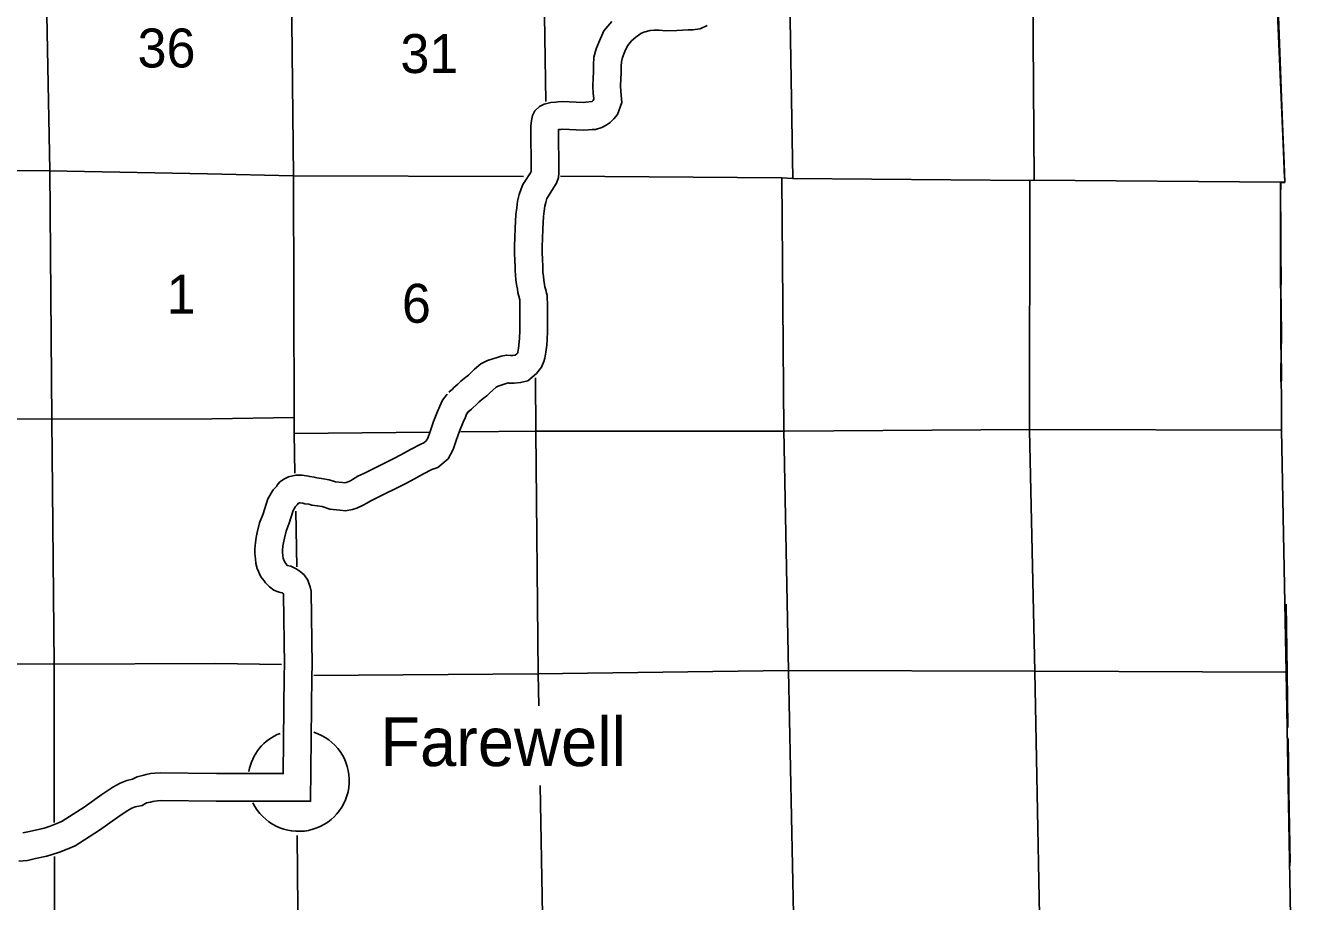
# Model space of a CAD drawing. Extents: x 77230 to 630905, y 790554 to 1662844.
# Drawn here: x 474126 to 501624, y 1600152 to 1619160 of the extents above; entities that cross this region are included whole.
import ezdxf

# ---------------------------------------------------------------- set-up
doc = ezdxf.new("R2010")
doc.units = 0
for name, color, linetype in [('Level 15', 7, 'Continuous'), ('Level 16', 7, 'Continuous'), ('Level 18', 7, 'Continuous'), ('Level 22', 7, 'Continuous'), ('Level 26', 7, 'Continuous'), ('Level 43', 7, 'Continuous')]:
    doc.layers.add(name, color=color, linetype=linetype)

msp = doc.modelspace()

# ---------------------------------------------------------------- linework, layer by layer
at = {"layer": 'Level 15'}
for points in [[(479717, 1636912), (479774, 1631910), (479834, 1626579), (479884, 1621257), (479943, 1615888), (479960, 1610654), (479956, 1610308), (479974, 1609444)], [(464632, 1616087), (469369, 1616046), (474647, 1616003), (478077, 1615938)], [(478077, 1615938), (479939, 1615894), (484938, 1615884)], [(485740, 1615890), (490537, 1615850), (490777, 1615840), (495918, 1615795), (496015, 1615798), (501358, 1615756)], [(479992, 1608622), (480018, 1607418)], [(480025, 1601590), (480035, 1600000), (480046, 1599824), (480090, 1596156)]]:
    msp.add_lwpolyline(points, dxfattribs=at)
at = {"layer": 'Level 16'}
for points in [[(474459, 1636579), (474453, 1631902), (474480, 1626616), (474553, 1621263), (474655, 1616017), (474702, 1610602), (474752, 1605292), (474754, 1601870)], [(485146, 1635809), (485219, 1631833), (485283, 1626572), (485361, 1621247), (485418, 1617511)], [(490692, 1621012), (490777, 1615840)], [(495988, 1619908), (496015, 1615798)], [(490537, 1615850), (490585, 1610380), (490684, 1605162), (490796, 1599882), (490880, 1596386)], [(495918, 1615795), (495916, 1610368), (496027, 1605143), (496129, 1599851), (496195, 1596422)], [(485198, 1611511), (485206, 1610350), (485251, 1605100), (485264, 1604399)], [(478175, 1610622), (474718, 1610618), (469378, 1610658), (466118, 1610615)], [(479960, 1610654), (478175, 1610622)], [(482911, 1610334), (479956, 1610308)], [(501382, 1610380), (495921, 1610392), (490603, 1610358), (485220, 1610355), (483573, 1610340)], [(478249, 1605315), (474744, 1605306), (469453, 1605337), (464146, 1605335), (461603, 1605328)], [(479681, 1605293), (478249, 1605315)], [(501484, 1605131), (496035, 1605152), (490680, 1605168), (485242, 1605090), (480383, 1605056)], [(485295, 1602672), (485345, 1599863), (485400, 1596307)], [(474755, 1601128), (474756, 1599966), (474801, 1596072)]]:
    msp.add_lwpolyline(points, dxfattribs=at)
at = {"layer": 'Level 18'}
msp.add_lwpolyline([(501006, 1635374), (501100, 1631624), (501214, 1626409), (501225, 1621103), (501451, 1615759), (501358, 1615756), (501382, 1610380), (501484, 1605131), (501575, 1599831), (501624, 1596559)], dxfattribs=at)
msp.add_lwpolyline([(501006, 1635374), (501100, 1631624), (501214, 1626409), (501225, 1621103), (501451, 1615759), (501358, 1615756), (501382, 1610380), (501484, 1605131), (501575, 1599831), (501624, 1596559)], dxfattribs=at)
at = {"layer": 'Level 22'}
for points in [[(486850, 1619244), (486677, 1619038), (486582, 1618822), (486513, 1618649), (486463, 1618467), (486452, 1618294), (486452, 1618142), (486445, 1618019), (486442, 1617832), (486450, 1617686), (486458, 1617569), (486445, 1617533), (486425, 1617511), (486424, 1617510), (486286, 1617490), (486227, 1617487), (485771, 1617507), (485684, 1617500), (485633, 1617494), (485525, 1617488), (485384, 1617449), (485283, 1617401), (485180, 1617303), (485133, 1617206), (485105, 1617096), (485091, 1616971), (485099, 1615986), (485084, 1615959), (485046, 1615897), (485005, 1615835), (484922, 1615711), (484882, 1615612), (484840, 1615489), (484804, 1615343), (484787, 1615205), (484769, 1615060), (484757, 1614763), (484749, 1614558), (484743, 1614380), (484737, 1614226), (484748, 1614051), (484753, 1613932), (484751, 1613845), (484760, 1613744), (484771, 1613642), (484783, 1613541), (484802, 1613437), (484814, 1613367), (484834, 1613285), (484852, 1613203), (484852, 1613201), (484852, 1613201), (484857, 1613117), (484856, 1612953), (484856, 1612769), (484855, 1612533), (484851, 1612375), (484843, 1612294), (484823, 1612156), (484811, 1612069), (484809, 1612062), (484804, 1612049), (484792, 1612034), (484754, 1612003), (484707, 1611998), (484652, 1611999), (484564, 1612007), (484447, 1611987), (484362, 1611955), (484272, 1611927), (484155, 1611890), (484012, 1611815), (483869, 1611701), (483775, 1611609), (483740, 1611574), (483683, 1611530), (483576, 1611439), (483512, 1611379), (483425, 1611303), (483391, 1611269), (483315, 1611200)], [(486850, 1619244), (486677, 1619038), (486582, 1618822), (486513, 1618649), (486463, 1618467), (486452, 1618294), (486452, 1618142), (486445, 1618019), (486442, 1617832), (486450, 1617686), (486458, 1617569), (486445, 1617533), (486425, 1617511), (486424, 1617510), (486286, 1617490), (486227, 1617487), (485771, 1617507), (485684, 1617500), (485633, 1617494), (485525, 1617488), (485384, 1617449), (485283, 1617401), (485180, 1617303), (485133, 1617206), (485105, 1617096), (485091, 1616971), (485099, 1615986), (485084, 1615959), (485046, 1615897), (485005, 1615835), (484922, 1615711), (484882, 1615612), (484840, 1615489), (484804, 1615343), (484787, 1615205), (484769, 1615060), (484757, 1614763), (484749, 1614558), (484743, 1614380), (484737, 1614226), (484748, 1614051), (484753, 1613932), (484751, 1613845), (484760, 1613744), (484771, 1613642), (484783, 1613541), (484802, 1613437), (484814, 1613367), (484834, 1613285), (484852, 1613203), (484852, 1613201), (484852, 1613201), (484857, 1613117), (484856, 1612953), (484856, 1612769), (484855, 1612533), (484851, 1612375), (484843, 1612294), (484823, 1612156), (484811, 1612069), (484809, 1612062), (484804, 1612049), (484792, 1612034), (484754, 1612003), (484707, 1611998), (484652, 1611999), (484564, 1612007), (484447, 1611987), (484362, 1611955), (484272, 1611927), (484155, 1611890), (484012, 1611815), (483869, 1611701), (483775, 1611609), (483740, 1611574), (483683, 1611530), (483576, 1611439), (483512, 1611379), (483425, 1611303), (483391, 1611269), (483315, 1611200)], [(488923, 1619153), (488765, 1619083), (488608, 1619066), (488506, 1619060), (488264, 1619050), (488022, 1619043), (487880, 1619052), (487771, 1619055), (487680, 1619046), (487549, 1619011), (487481, 1618982), (487373, 1618905), (487281, 1618824), (487192, 1618718), (487135, 1618589), (487083, 1618459), (487058, 1618369), (487052, 1618273), (487052, 1618124), (487045, 1617999), (487043, 1617845), (487049, 1617722), (487065, 1617487), (486973, 1617223), (486893, 1617132), (486815, 1617050), (486726, 1616991), (486636, 1616945), (486498, 1616901), (486422, 1616904), (486346, 1616892), (486230, 1616886), (485780, 1616906), (485743, 1616903), (485692, 1616897), (485699, 1615989), (485699, 1615953), (485691, 1615856), (485648, 1615738), (485602, 1615656), (485553, 1615576), (485506, 1615505), (485455, 1615428), (485444, 1615402), (485416, 1615320), (485395, 1615234), (485382, 1615131), (485367, 1615011), (485356, 1614739), (485348, 1614535), (485342, 1614360), (485338, 1614234), (485347, 1614080), (485353, 1613939), (485352, 1613865), (485357, 1613803), (485367, 1613712), (485377, 1613629), (485392, 1613541), (485401, 1613491), (485419, 1613421), (485434, 1613348), (485447, 1613305), (485451, 1613237), (485457, 1613132), (485456, 1612952), (485456, 1612767), (485455, 1612523), (485450, 1612340), (485439, 1612224), (485418, 1612073), (485400, 1611944), (485378, 1611870), (485329, 1611743), (485219, 1611608), (485030, 1611452), (484870, 1611411), (484729, 1611398), (484620, 1611400), (484595, 1611402), (484558, 1611388), (484453, 1611355), (484386, 1611334), (484341, 1611310), (484266, 1611250), (484198, 1611184), (484141, 1611126), (484063, 1611065), (483975, 1610990), (483913, 1610932), (483837, 1610866), (483807, 1610835), (483716, 1610754)], [(488923, 1619153), (488765, 1619083), (488608, 1619066), (488506, 1619060), (488264, 1619050), (488022, 1619043), (487880, 1619052), (487771, 1619055), (487680, 1619046), (487549, 1619011), (487481, 1618982), (487373, 1618905), (487281, 1618824), (487192, 1618718), (487135, 1618589), (487083, 1618459), (487058, 1618369), (487052, 1618273), (487052, 1618124), (487045, 1617999), (487043, 1617845), (487049, 1617722), (487065, 1617487), (486973, 1617223), (486893, 1617132), (486815, 1617050), (486726, 1616991), (486636, 1616945), (486498, 1616901), (486422, 1616904), (486346, 1616892), (486230, 1616886), (485780, 1616906), (485743, 1616903), (485692, 1616897), (485699, 1615989), (485699, 1615953), (485691, 1615856), (485648, 1615738), (485602, 1615656), (485553, 1615576), (485506, 1615505), (485455, 1615428), (485444, 1615402), (485416, 1615320), (485395, 1615234), (485382, 1615131), (485367, 1615011), (485356, 1614739), (485348, 1614535), (485342, 1614360), (485338, 1614234), (485347, 1614080), (485353, 1613939), (485352, 1613865), (485357, 1613803), (485367, 1613712), (485377, 1613629), (485392, 1613541), (485401, 1613491), (485419, 1613421), (485434, 1613348), (485447, 1613305), (485451, 1613237), (485457, 1613132), (485456, 1612952), (485456, 1612767), (485455, 1612523), (485450, 1612340), (485439, 1612224), (485418, 1612073), (485400, 1611944), (485378, 1611870), (485329, 1611743), (485219, 1611608), (485030, 1611452), (484870, 1611411), (484729, 1611398), (484620, 1611400), (484595, 1611402), (484558, 1611388), (484453, 1611355), (484386, 1611334), (484341, 1611310), (484266, 1611250), (484198, 1611184), (484141, 1611126), (484063, 1611065), (483975, 1610990), (483913, 1610932), (483837, 1610866), (483807, 1610835), (483716, 1610754)], [(483277, 1611159), (483178, 1611030), (483122, 1610901), (483072, 1610785), (482985, 1610568), (482911, 1610350), (482859, 1610207), (482826, 1610146), (482775, 1610103), (482704, 1610078), (482480, 1609958), (482288, 1609853), (482110, 1609759), (481471, 1609439), (481337, 1609380), (481226, 1609309), (481180, 1609283), (481108, 1609249), (481089, 1609244), (481051, 1609237), (481011, 1609242), (480858, 1609255), (480717, 1609303), (480549, 1609334), (480449, 1609345), (480393, 1609360), (480299, 1609374), (480271, 1609380), (480132, 1609406), (479998, 1609401), (479835, 1609363), (479746, 1609325), (479645, 1609256), (479591, 1609183), (479573, 1609159), (479561, 1609143), (479505, 1609081), (479389, 1608890), (479285, 1608564), (479208, 1608369), (479159, 1608160), (479137, 1608050), (479117, 1607940), (479105, 1607801), (479106, 1607705), (479119, 1607588), (479128, 1607489), (479159, 1607377), (479238, 1607195), (479308, 1607112), (479336, 1607065), (479377, 1607025), (479420, 1606980), (479518, 1606909), (479589, 1606882), (479655, 1606860), (479696, 1606851), (479706, 1606847), (479720, 1606838), (479725, 1606822), (479726, 1606817), (479747, 1605283), (479739, 1605064), (479721, 1602931), (478270, 1602932)], [(483277, 1611159), (483178, 1611030), (483122, 1610901), (483072, 1610785), (482985, 1610568), (482911, 1610350), (482859, 1610207), (482826, 1610146), (482775, 1610103), (482704, 1610078), (482480, 1609958), (482288, 1609853), (482110, 1609759), (481471, 1609439), (481337, 1609380), (481226, 1609309), (481180, 1609283), (481108, 1609249), (481089, 1609244), (481051, 1609237), (481011, 1609242), (480858, 1609255), (480717, 1609303), (480549, 1609334), (480449, 1609345), (480393, 1609360), (480299, 1609374), (480271, 1609380), (480132, 1609406), (479998, 1609401), (479835, 1609363), (479746, 1609325), (479645, 1609256), (479591, 1609183), (479573, 1609159), (479561, 1609143), (479505, 1609081), (479389, 1608890), (479285, 1608564), (479208, 1608369), (479159, 1608160), (479137, 1608050), (479117, 1607940), (479105, 1607801), (479106, 1607705), (479119, 1607588), (479128, 1607489), (479159, 1607377), (479238, 1607195), (479308, 1607112), (479336, 1607065), (479377, 1607025), (479420, 1606980), (479518, 1606909), (479589, 1606882), (479655, 1606860), (479696, 1606851), (479706, 1606847), (479720, 1606838), (479725, 1606822), (479726, 1606817), (479747, 1605283), (479739, 1605064), (479721, 1602931), (478270, 1602932)], [(483754, 1610795), (483699, 1610723), (483673, 1610662), (483625, 1610554), (483548, 1610360), (483477, 1610152), (483408, 1609961), (483300, 1609760), (483077, 1609572), (482945, 1609527), (482766, 1609431), (482572, 1609324), (482383, 1609225), (481727, 1608896), (481621, 1608849), (481534, 1608794), (481456, 1608750), (481321, 1608686), (481224, 1608658), (481070, 1608631), (480950, 1608645), (480734, 1608664), (480566, 1608721), (480460, 1608740), (480339, 1608754), (480275, 1608771), (480189, 1608783), (480149, 1608792), (480087, 1608804), (480077, 1608804), (480052, 1608798), (480052, 1608798), (480024, 1608761), (479989, 1608722), (479939, 1608639), (479850, 1608362), (479782, 1608190), (479746, 1608034), (479726, 1607936), (479712, 1607861), (479706, 1607779), (479706, 1607739), (479716, 1607647), (479720, 1607599), (479726, 1607579), (479754, 1607513), (479798, 1607461), (479810, 1607440), (479885, 1607426), (480000, 1607372), (480086, 1607315), (480174, 1607241), (480256, 1607122), (480284, 1607042), (480305, 1606978), (480325, 1606884), (480347, 1605277), (480339, 1605051), (480316, 1602331), (478270, 1602332)], [(483754, 1610795), (483699, 1610723), (483673, 1610662), (483625, 1610554), (483548, 1610360), (483477, 1610152), (483408, 1609961), (483300, 1609760), (483077, 1609572), (482945, 1609527), (482766, 1609431), (482572, 1609324), (482383, 1609225), (481727, 1608896), (481621, 1608849), (481534, 1608794), (481456, 1608750), (481321, 1608686), (481224, 1608658), (481070, 1608631), (480950, 1608645), (480734, 1608664), (480566, 1608721), (480460, 1608740), (480339, 1608754), (480275, 1608771), (480189, 1608783), (480149, 1608792), (480087, 1608804), (480077, 1608804), (480052, 1608798), (480052, 1608798), (480024, 1608761), (479989, 1608722), (479939, 1608639), (479850, 1608362), (479782, 1608190), (479746, 1608034), (479726, 1607936), (479712, 1607861), (479706, 1607779), (479706, 1607739), (479716, 1607647), (479720, 1607599), (479726, 1607579), (479754, 1607513), (479798, 1607461), (479810, 1607440), (479885, 1607426), (480000, 1607372), (480086, 1607315), (480174, 1607241), (480256, 1607122), (480284, 1607042), (480305, 1606978), (480325, 1606884), (480347, 1605277), (480339, 1605051), (480316, 1602331), (478270, 1602332)], [(478273, 1602932), (477051, 1602947), (476939, 1602938), (476844, 1602929), (476748, 1602908), (476695, 1602893), (476551, 1602860), (476448, 1602807), (476330, 1602779), (476183, 1602722), (476023, 1602634), (475789, 1602479), (475399, 1602199), (475082, 1601999), (474926, 1601897), (474844, 1601863), (474666, 1601791), (474531, 1601749), (474442, 1601722), (474215, 1601672), (474075, 1601641)], [(478266, 1602332), (477071, 1602347), (476992, 1602341), (476938, 1602335), (476895, 1602326), (476844, 1602311), (476757, 1602292), (476658, 1602241), (476509, 1602205), (476437, 1602177), (476335, 1602121), (476130, 1601985), (475734, 1601701), (475406, 1601494), (475209, 1601365), (475073, 1601308), (474869, 1601225), (474705, 1601174), (474591, 1601141), (474345, 1601087), (474173, 1601048), (473988, 1601028)]]:
    msp.add_lwpolyline(points, dxfattribs=at)
at = {"layer": 'Level 26'}
for start, end in [(111.2653, 169.5598), (205.761, 72.678)]:
    msp.add_arc((480055, 1602777), 1100, start, end, dxfattribs=at)
at = {"layer": 'Level 43'}
msp.add_line((501367, 1615751), (501452, 1615752), dxfattribs=at)
for points in [[(501245, 1623346), (501248, 1622638), (501247, 1621106), (501256, 1620797), (501330, 1618968), (501327, 1618811), (501360, 1618045), (501440, 1616160), (501452, 1615752)], [(501252, 1621110), (501444, 1615844)], [(501367, 1615751), (501360, 1615420), (501363, 1613673), (501370, 1613235), (501368, 1612128)], [(501361, 1615672), (501367, 1614565)], [(501369, 1614314), (501373, 1613535)], [(501375, 1613222), (501380, 1612257)], [(501367, 1611834), (501366, 1611427)], [(501383, 1611817), (501385, 1611448)], [(501475, 1606545), (501505, 1605136), (501521, 1603953)], [(501482, 1606603), (501506, 1605120), (501518, 1603929)], [(501521, 1603706), (501569, 1601003)], [(501525, 1603679), (501563, 1600927)]]:
    msp.add_lwpolyline(points, dxfattribs=at)

# ---------------------------------------------------------------- texts
at = {"layer": 'Level 16'}
for s, height, p in [('36', 844.8, (476561, 1618246)), ('31', 844.8, (482264, 1618125)), ('1', 845, (477193, 1612905)), ('6', 845, (482297, 1612708))]:
    msp.add_text(s, height=height, dxfattribs=at).set_placement(p)
at = {"layer": 'Level 26'}
msp.add_text('Farewell', height=1056, dxfattribs=at).set_placement((481826, 1603092))

doc.saveas('drawing.dxf')
